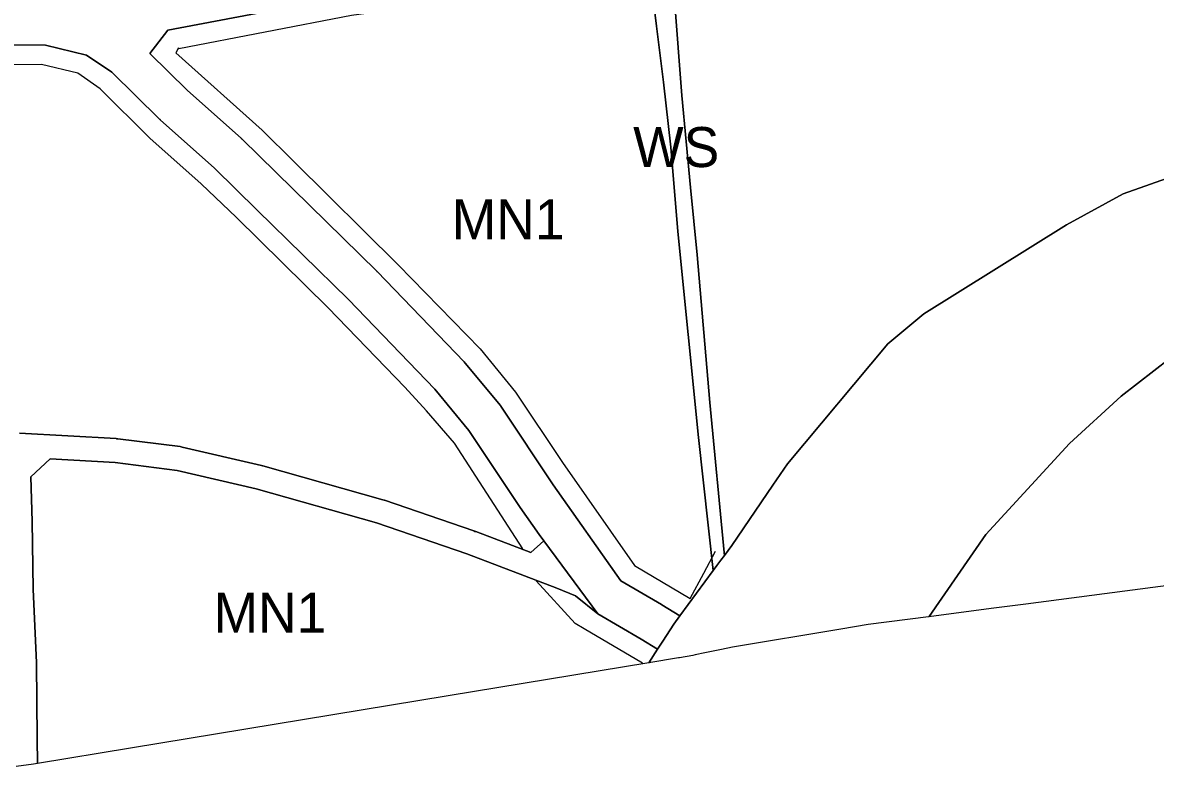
# Model space of a CAD drawing. Extents: x -284239 to -281592, y 34477 to 37267.
# Drawn here: x -282826.9 to -282543.7, y 34652.1 to 34838 of the extents above; entities that cross this region are included whole.
import ezdxf

# ---------------------------------------------------------------- set-up
doc = ezdxf.new("R2010")
doc.units = 0
for name, color, linetype in [('linie_rozgraniczajace', 7, 'Continuous'), ('linie_zabudowy_nieprzekraczalne', 7, 'Continuous'), ('oznaczenia_przeznaczen', 7, 'Continuous')]:
    doc.layers.add(name, color=color, linetype=linetype)

msp = doc.modelspace()

# ---------------------------------------------------------------- linework, layer by layer
at = {"layer": 'linie_rozgraniczajace'}
for points in [[(-282669.71, 34847.3), (-282668.44, 34837.11), (-282666.69, 34823.06), (-282664.82, 34806.88), (-282663.1, 34785.8), (-282657.911, 34734.273), (-282654.248, 34701.031), (-282662.611, 34689.682), (-282667.136, 34692.465), (-282667.191, 34692.493), (-282667.219, 34692.514), (-282677.388, 34698.446), (-282694.253, 34722.44), (-282707.184, 34741.835), (-282707.403, 34742.102), (-282707.489, 34742.246), (-282716.286, 34752.896), (-282716.537, 34753.174), (-282738.305, 34775.739), (-282738.363, 34775.778), (-282738.403, 34775.837), (-282759.418, 34796.44), (-282772.071, 34808.844), (-282772.179, 34808.915), (-282772.241, 34809.003), (-282785.782, 34821.098), (-282795.166, 34830.279), (-282790.654, 34836.076), (-282743.417, 34845.102)], [(-282663.971, 34843.747), (-282662.112, 34819.789), (-282659.938, 34796.782), (-282658.24, 34779.91), (-282655.11, 34743.018), (-282651.516, 34705.538), (-282651.445, 34704.836), (-282652.333, 34703.631), (-282653.317, 34702.294), (-282654.248, 34701.031), (-282657.911, 34734.273), (-282663.1, 34785.8), (-282664.82, 34806.88), (-282666.69, 34823.06), (-282668.44, 34837.11), (-282669.71, 34847.3)], [(-282743.417, 34845.102), (-282790.654, 34836.076), (-282795.166, 34830.279), (-282785.782, 34821.098), (-282772.241, 34809.003), (-282772.179, 34808.915), (-282772.071, 34808.844), (-282759.418, 34796.44), (-282738.403, 34775.837), (-282738.363, 34775.778), (-282738.305, 34775.739), (-282716.537, 34753.174), (-282716.286, 34752.896), (-282707.489, 34742.246), (-282707.403, 34742.102), (-282707.184, 34741.835), (-282694.253, 34722.44), (-282677.388, 34698.446), (-282667.219, 34692.514), (-282667.191, 34692.493), (-282667.136, 34692.465), (-282662.611, 34689.682), (-282664.098, 34687.664), (-282666.862, 34683.38), (-282668.155, 34681.375), (-282672.299, 34683.901), (-282683.085, 34690.193), (-282696.59, 34708.458), (-282697.783, 34710.071), (-282702.498, 34716.79), (-282715.362, 34736.075), (-282723.873, 34746.378), (-282745.453, 34768.745), (-282768.293, 34791.136), (-282778.989, 34801.622), (-282792.529, 34813.716), (-282792.589, 34813.801), (-282792.695, 34813.871), (-282804.678, 34825.597), (-282810.968, 34829.865), (-282821.234, 34832.359), (-282838.113, 34832.486)], [(-282520.433, 34806.265), (-282551.698, 34795.154), (-282565.91, 34787.402), (-282601.567, 34765.181), (-282610.611, 34757.688), (-282635.675, 34727.714), (-282639.344, 34722.358), (-282649.628, 34707.302), (-282651.445, 34704.836), (-282651.516, 34705.538), (-282655.11, 34743.018), (-282658.24, 34779.91), (-282659.938, 34796.782), (-282662.112, 34819.789), (-282663.971, 34843.747)], [(-282838.113, 34832.486), (-282821.234, 34832.359), (-282810.968, 34829.865), (-282804.678, 34825.597), (-282792.695, 34813.871), (-282792.589, 34813.801), (-282792.529, 34813.716), (-282778.989, 34801.622), (-282768.293, 34791.136), (-282745.453, 34768.745), (-282723.873, 34746.378), (-282715.362, 34736.075), (-282702.498, 34716.79), (-282697.783, 34710.071), (-282696.59, 34708.458), (-282699.896, 34705.565), (-282713.614, 34710.779), (-282713.901, 34710.831), (-282714.092, 34710.951), (-282736.474, 34718.628), (-282736.528, 34718.637), (-282736.846, 34718.747), (-282766.885, 34727.227), (-282767, 34727.243), (-282767.236, 34727.318), (-282787.02, 34731.904), (-282787.341, 34731.941), (-282787.566, 34732.001), (-282803.114, 34733.961), (-282803.497, 34733.984), (-282803.55, 34733.997), (-282827.697, 34735.363)], [(-282670.361, 34677.956), (-282668.155, 34681.375), (-282666.862, 34683.38), (-282664.098, 34687.664), (-282662.611, 34689.682), (-282654.248, 34701.031), (-282653.317, 34702.294), (-282652.333, 34703.631), (-282651.445, 34704.836), (-282649.628, 34707.302), (-282639.344, 34722.358), (-282635.675, 34727.714), (-282610.611, 34757.688), (-282601.567, 34765.181), (-282565.91, 34787.402), (-282551.698, 34795.154), (-282520.433, 34806.265)], [(-282535.937, 34757.3), (-282552.215, 34744.639), (-282565.135, 34732.753), (-282586.064, 34710.015), (-282600.272, 34689.573), (-282600.342, 34689.463), (-282600.44, 34689.45), (-282615.48, 34687.56), (-282622.32, 34686.42), (-282649.43, 34681.9), (-282652.2, 34681.32), (-282656.31, 34680.47), (-282658.799, 34679.943), (-282659.38, 34679.82)], [(-282540.45, 34697.3), (-282551.35, 34695.9), (-282576.1, 34692.63), (-282584.72, 34691.51), (-282600.342, 34689.463), (-282600.272, 34689.573), (-282586.064, 34710.015), (-282565.135, 34732.753), (-282552.215, 34744.639), (-282535.937, 34757.3)], [(-282827.697, 34735.363), (-282803.55, 34733.997), (-282803.497, 34733.984), (-282803.114, 34733.961), (-282787.566, 34732.001), (-282787.341, 34731.941), (-282787.02, 34731.904), (-282767.236, 34727.318), (-282767, 34727.243), (-282766.885, 34727.227), (-282736.846, 34718.747), (-282736.528, 34718.637), (-282736.474, 34718.628), (-282714.092, 34710.951), (-282713.901, 34710.831), (-282713.614, 34710.779), (-282699.896, 34705.565), (-282696.59, 34708.458), (-282683.085, 34690.193), (-282688.717, 34694.678), (-282693.34, 34696.654), (-282715.87, 34705.218), (-282738.499, 34712.98), (-282768.579, 34721.471), (-282788.336, 34726.05), (-282803.824, 34728.003), (-282820.096, 34728.924), (-282824.897, 34724.437), (-282824.603, 34713.311), (-282824.603, 34713.283), (-282824.326, 34696.393), (-282823.495, 34677.959), (-282823.504, 34677.907), (-282823.492, 34677.848), (-282823.338, 34659.024), (-282823.194, 34652.848), (-282824.22, 34652.68), (-282828.53, 34652.1)], [(-282659.38, 34679.82), (-282662.69, 34679.22), (-282662.951, 34679.177), (-282670.361, 34677.956)]]:
    msp.add_lwpolyline(points, dxfattribs=at)
msp.add_lwpolyline([(-282824.897, 34724.437), (-282820.096, 34728.924), (-282803.824, 34728.003), (-282788.336, 34726.05), (-282768.579, 34721.471), (-282738.499, 34712.98), (-282715.87, 34705.218), (-282693.34, 34696.654), (-282688.717, 34694.678), (-282683.085, 34690.193), (-282672.299, 34683.901), (-282668.155, 34681.375), (-282670.361, 34677.956), (-282720.57, 34669.68), (-282800, 34656.65), (-282823.194, 34652.848), (-282823.338, 34659.024), (-282823.492, 34677.848), (-282823.504, 34677.907), (-282823.495, 34677.959), (-282824.326, 34696.393), (-282824.603, 34713.283), (-282824.603, 34713.311)], close=True, dxfattribs=at)
at = {"layer": 'linie_zabudowy_nieprzekraczalne'}
for points in [[(-282667.335, 34849.133), (-282717.739, 34843.445), (-282744.726, 34839.741), (-282787.849, 34831.45)], [(-282787.981, 34831.649), (-282788.642, 34830.458), (-282767.079, 34811.143), (-282759.141, 34803.272), (-282733.08, 34777.475), (-282712.574, 34756.441), (-282703.711, 34745.659), (-282691.937, 34728.064), (-282673.945, 34702.267), (-282660.055, 34694.065), (-282656.615, 34700.415), (-282653.705, 34705.839)], [(-282701.869, 34706.478), (-282718.924, 34732.893), (-282725.936, 34740.962), (-282731.36, 34746.849), (-282750.542, 34766.693), (-282773.429, 34789.249), (-282782.292, 34797.716), (-282795.125, 34809.093), (-282807.56, 34821.396), (-282813.116, 34825.365), (-282822.244, 34827.548), (-282842.221, 34827.415), (-282864.71, 34826.291), (-282899.371, 34826.158), (-282920.405, 34825.762), (-282935.619, 34825.365), (-282956.124, 34823.909), (-282978.089, 34823.469)], [(-282671.961, 34677.859), (-282686.536, 34686.458), (-282688.817, 34687.804), (-282698.532, 34698.483)]]:
    msp.add_lwpolyline(points, dxfattribs=at)

# ---------------------------------------------------------------- texts
at = {"layer": 'oznaczenia_przeznaczen'}
for s, p in [('WS', (-282674.274, 34801.88)), ('MN1', (-282719.653, 34783.782)), ('MN1', (-282779.22, 34685.488))]:
    msp.add_text(s, height=10, dxfattribs=at).set_placement(p)

doc.saveas('drawing.dxf')
